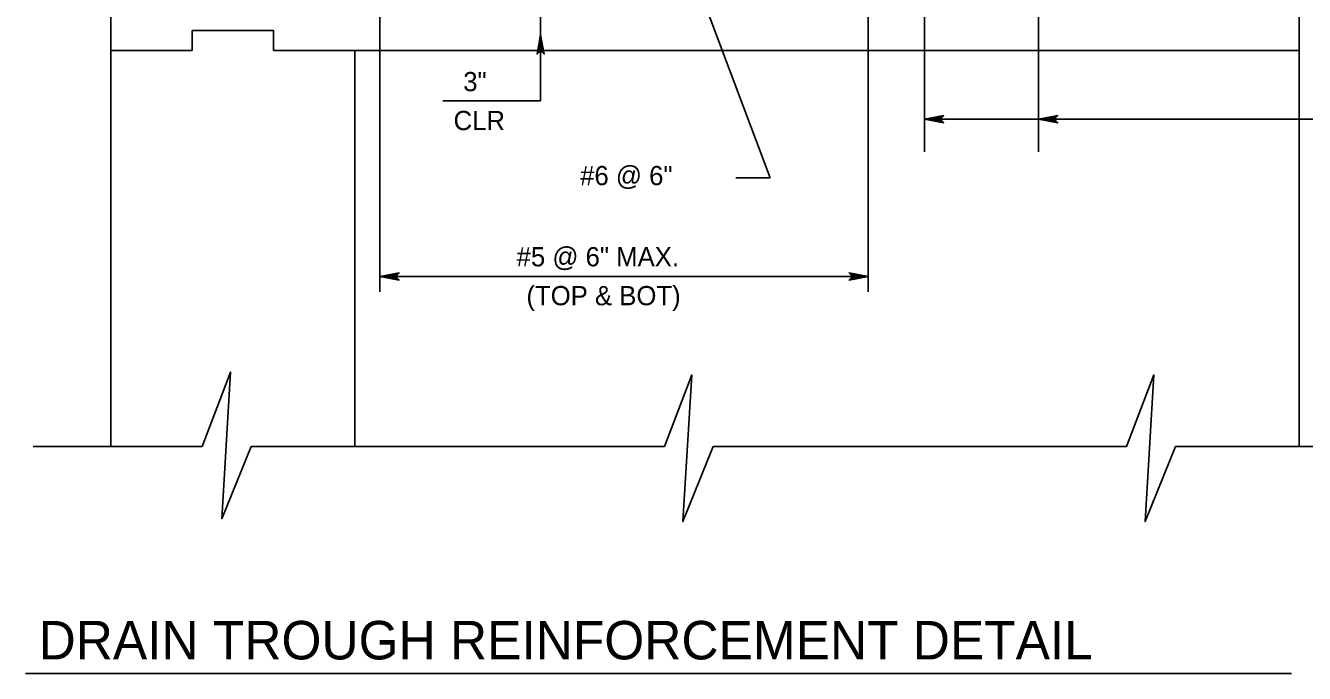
# Model space of a CAD drawing. Extents: x 636530 to 644067, y 294168 to 299122.
# Drawn here: x 639566.9 to 639766.4, y 295072.4 to 295173.5 of the extents above; entities that cross this region are included whole.
import ezdxf

# ---------------------------------------------------------------- set-up
doc = ezdxf.new("R2010")
doc.units = 0
doc.layers.add('1', color=7, linetype='Continuous')

msp = doc.modelspace()

# ---------------------------------------------------------------- linework, layer by layer
at = {"layer": '1'}
for p, q in [((639707.17, 295270.28), (639707.17, 295153.8)), ((639724.95, 295270.28), (639724.95, 295153.8)), ((639765.6, 295259.09), (639765.6, 295169.63)), ((639580.17, 295107.84), (639580.17, 295243.29)), ((639647.26, 295182.28), (639647.26, 295161.77)), ((639672.7, 295177.25), (639683.09, 295149.78)), ((639622.18, 295175.51), (639622.18, 295131.99)), ((639698.38, 295175.51), (639698.38, 295131.99)), ((639592.87, 295169.63), (639592.87, 295172.76)), ((639605.57, 295172.76), (639592.87, 295172.76)), ((639605.57, 295169.63), (639605.57, 295172.76)), ((639580.17, 295169.63), (639592.87, 295169.63)), ((639605.57, 295169.63), (639618.27, 295169.63)), ((639765.6, 295169.63), (639618.27, 295169.63)), ((639618.27, 295118.1), (639618.27, 295169.63)), ((639765.6, 295107.84), (639765.6, 295169.63)), ((639647.26, 295161.77), (639632, 295161.77)), ((639769.56, 295158.91), (639707.17, 295158.91)), ((639683.09, 295149.78), (639677.7, 295149.78)), ((639698.38, 295134.37), (639622.18, 295134.37)), ((639618.27, 295107.84), (639618.27, 295131.57)), ((639568.1, 295107.84), (639594.46, 295107.84)), ((639602.08, 295107.84), (639666.57, 295107.84)), ((639674.2, 295107.84), (639738.69, 295107.84)), ((639746.32, 295107.84), (639772.87, 295107.84)), ((639566.89, 295072.44), (639764.39, 295072.44))]:
    msp.add_line(p, q, dxfattribs=at)
for points in [[(639647.26, 295172.05), (639646.71, 295169.06), (639646.78, 295169.18), (639646.86, 295169.29), (639646.96, 295169.35), (639647.06, 295169.41), (639647.16, 295169.43), (639647.26, 295169.45), (639647.36, 295169.43), (639647.46, 295169.41), (639647.56, 295169.35), (639647.66, 295169.29), (639647.74, 295169.18), (639647.82, 295169.06), (639647.26, 295172.05), (639647.74, 295169.18), (639647.66, 295169.29), (639647.26, 295172.05), (639647.56, 295169.35), (639647.46, 295169.41), (639647.26, 295172.05), (639647.36, 295169.43), (639647.26, 295169.45), (639647.26, 295172.05), (639647.16, 295169.43), (639647.06, 295169.41), (639647.26, 295172.05), (639646.96, 295169.35), (639646.86, 295169.29), (639647.26, 295172.05), (639646.78, 295169.18)], [(639707.17, 295158.91), (639710.15, 295158.35), (639710.04, 295158.43), (639709.92, 295158.51), (639709.86, 295158.61), (639709.8, 295158.71), (639709.78, 295158.81), (639709.77, 295158.91), (639709.78, 295159.01), (639709.8, 295159.11), (639709.86, 295159.21), (639709.92, 295159.31), (639710.04, 295159.39), (639710.15, 295159.47), (639707.17, 295158.91), (639710.04, 295159.39), (639709.92, 295159.31), (639707.17, 295158.91), (639709.86, 295159.21), (639709.8, 295159.11), (639707.17, 295158.91), (639709.78, 295159.01), (639709.77, 295158.91), (639707.17, 295158.91), (639709.78, 295158.81), (639709.8, 295158.71), (639707.17, 295158.91), (639709.86, 295158.61), (639709.92, 295158.51), (639707.17, 295158.91), (639710.04, 295158.43)], [(639724.95, 295158.91), (639727.93, 295158.35), (639727.81, 295158.43), (639727.7, 295158.51), (639727.64, 295158.61), (639727.58, 295158.71), (639727.56, 295158.81), (639727.55, 295158.91), (639727.56, 295159.01), (639727.58, 295159.11), (639727.64, 295159.21), (639727.7, 295159.31), (639727.81, 295159.39), (639727.93, 295159.47), (639724.95, 295158.91), (639727.81, 295159.39), (639727.7, 295159.31), (639724.95, 295158.91), (639727.64, 295159.21), (639727.58, 295159.11), (639724.95, 295158.91), (639727.56, 295159.01), (639727.55, 295158.91), (639724.95, 295158.91), (639727.56, 295158.81), (639727.58, 295158.71), (639724.95, 295158.91), (639727.64, 295158.61), (639727.7, 295158.51), (639724.95, 295158.91), (639727.81, 295158.43)], [(639622.18, 295134.37), (639625.16, 295134.93), (639625.04, 295134.85), (639624.93, 295134.77), (639624.87, 295134.67), (639624.81, 295134.57), (639624.79, 295134.47), (639624.78, 295134.37), (639624.79, 295134.27), (639624.81, 295134.17), (639624.87, 295134.07), (639624.93, 295133.97), (639625.04, 295133.89), (639625.16, 295133.81), (639622.18, 295134.37), (639625.04, 295133.89), (639624.93, 295133.97), (639622.18, 295134.37), (639624.87, 295134.07), (639624.81, 295134.17), (639622.18, 295134.37), (639624.79, 295134.27), (639624.78, 295134.37), (639622.18, 295134.37), (639624.79, 295134.47), (639624.81, 295134.57), (639622.18, 295134.37), (639624.87, 295134.67), (639624.93, 295134.77), (639622.18, 295134.37), (639625.04, 295134.85)], [(639698.38, 295134.37), (639695.39, 295133.81), (639695.51, 295133.89), (639695.62, 295133.97), (639695.68, 295134.07), (639695.74, 295134.17), (639695.76, 295134.27), (639695.78, 295134.37), (639695.76, 295134.47), (639695.74, 295134.57), (639695.68, 295134.67), (639695.62, 295134.77), (639695.51, 295134.85), (639695.39, 295134.93), (639698.38, 295134.37), (639695.51, 295134.85), (639695.62, 295134.77), (639698.38, 295134.37), (639695.68, 295134.67), (639695.74, 295134.57), (639698.38, 295134.37), (639695.76, 295134.47), (639695.78, 295134.37), (639698.38, 295134.37), (639695.76, 295134.27), (639695.74, 295134.17), (639698.38, 295134.37), (639695.68, 295134.07), (639695.62, 295133.97), (639698.38, 295134.37), (639695.51, 295133.89)], [(639602.08, 295107.84), (639597.5, 295096.58), (639598.89, 295119.44), (639594.46, 295107.84)], [(639674.2, 295107.84), (639669.45, 295096.14), (639670.83, 295119), (639666.57, 295107.84)], [(639746.32, 295107.84), (639741.57, 295096.14), (639742.95, 295119), (639738.69, 295107.84)]]:
    msp.add_lwpolyline(points, dxfattribs=at)

# ---------------------------------------------------------------- texts
for s, height, p in [('3"', 3, (639635.18, 295163.27)), ('CLR', 3, (639633.67, 295157.2)), ('#6 @ 6"', 3, (639653.42, 295148.61)), ('#5 @ 6" MAX.', 3, (639643.51, 295135.95)), ('(TOP & BOT)', 3, (639645.04, 295129.88)), ('DRAIN TROUGH REINFORCEMENT DETAIL', 6, (639568.93, 295074.63))]:
    msp.add_text(s, height=height, dxfattribs=at).set_placement(p)

doc.saveas('drawing.dxf')
